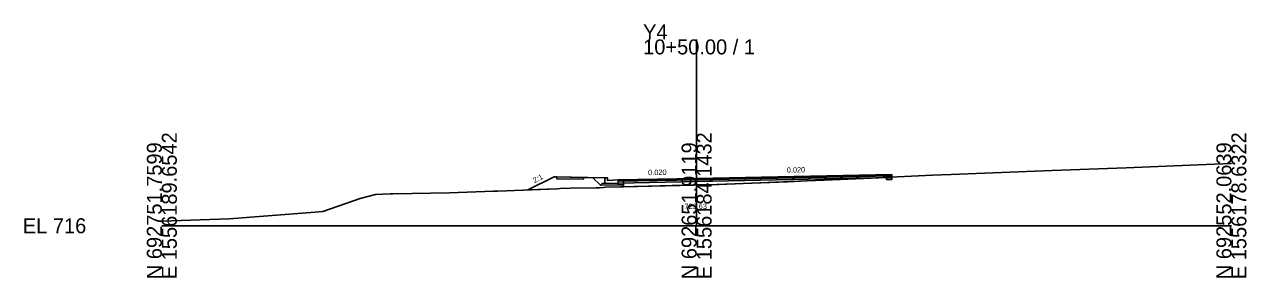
# Model space of a CAD drawing. Extents: x -26 to 203, y -10 to 1521.
# Drawn here: x -25.7 to 202.8, y -9.7 to 37.7 of the extents above; entities that cross this region are included whole.
import ezdxf

# ---------------------------------------------------------------- set-up
doc = ezdxf.new("R2010")
doc.units = 0
for name, color, linetype in [('Exist CMT Pavement', 7, 'Continuous'), ('Exist Cross Section Cell', 7, 'Continuous'), ('Exist XS Center Line Elevation Label', 7, 'Continuous'), ('Exist XS Ground Line', 7, 'Continuous'), ('Prop CMT Conc Surface', 7, 'Continuous'), ('Prop CMT Concrete Structures', 7, 'Continuous'), ('Prop CMT Pvmt Course 1', 7, 'Continuous'), ('Prop CMT Pvmt Course 1 CG', 7, 'Continuous'), ('Prop CMT Pvmt Course 2', 7, 'Continuous'), ('Prop CMT Pvmt Course 3', 7, 'Continuous'), ('Prop CMT Pvmt Surface', 7, 'Continuous'), ('Prop CMT Slope Grass', 7, 'Continuous'), ('Prop CMT Subgrade Earthwork', 7, 'Continuous'), ('Prop XS Earthwork Shape', 7, 'Continuous'), ('Prop XS SE Text', 7, 'Continuous'), ('Prop XS Side Slope Text', 7, 'Continuous')]:
    doc.layers.add(name, color=color, linetype=linetype)

msp = doc.modelspace()

# ---------------------------------------------------------------- linework, layer by layer
at = {"layer": 'Exist CMT Pavement'}
for p, q in [((86.34, 7.3), (102.09, 7.68)), ((102.09, 7.68), (117, 8.23)), ((117, 8.23), (120.67, 8.37)), ((120.67, 8.37), (135.49, 9.05))]:
    msp.add_line(p, q, dxfattribs=at)
at = {"layer": 'Exist Cross Section Cell'}
for p, q in [((100, 0), (100, 34.85)), ((0, 0), (100, 0)), ((100, 0), (200, 0))]:
    msp.add_line(p, q, dxfattribs=at)
at = {"layer": 'Exist XS Ground Line'}
msp.add_lwpolyline([(0, 0.86), (12.59, 1.28), (27.87, 2.46), (30.08, 2.69), (37.1, 5.09), (39.98, 5.86), (42.7, 5.95), (43.2, 5.97), (53.82, 6.17), (62.02, 6.47), (62.76, 6.48), (73.98, 6.9), (75.05, 7.01), (75.58, 6.98), (76.44, 7), (81.17, 7.11), (81.83, 7.11), (82.56, 7.14), (82.96, 7.21), (85.74, 7.28), (88.27, 7.36), (88.64, 7.37), (100, 7.63), (104.18, 7.73), (113.33, 8.09), (120.67, 8.37), (125.41, 8.59), (138.9, 9.21), (144.1, 9.43), (147.58, 9.56), (166.4, 10.31), (180.32, 10.86), (195.29, 11.45), (200, 11.62)], dxfattribs=at)
at = {"layer": 'Prop CMT Conc Surface'}
for points in [[(78.84, 9.03), (73.84, 9.13)], [(83.34, 8.44), (83.34, 8.94), (82.84, 8.94)], [(85.34, 8.56), (83.34, 8.44)]]:
    msp.add_lwpolyline(points, dxfattribs=at)
at = {"layer": 'Prop CMT Concrete Structures'}
for points in [[(73.84, 8.8), (73.84, 9.13)], [(73.84, 9.13), (78.84, 9.03)], [(78.84, 8.7), (73.84, 8.8)], [(78.84, 9.03), (78.84, 8.7)], [(85.34, 8.56), (83.34, 8.44), (83.34, 8.94), (82.84, 8.94)], [(82.84, 8.94), (82.84, 7.93), (85.34, 7.98)], [(85.34, 7.98), (85.34, 8.56)]]:
    msp.add_lwpolyline(points, dxfattribs=at)
at = {"layer": 'Prop CMT Pvmt Course 1'}
for p, q in [((100, 8.73), (135.49, 9.44)), ((135.49, 9.44), (135.49, 9.32)), ((86.34, 8.46), (100, 8.73)), ((86.34, 8.46), (86.34, 8.33))]:
    msp.add_line(p, q, dxfattribs=at)
for points in [[(100, 8.86), (136.49, 9.59)], [(136.49, 9.34), (100, 8.61)], [(136.49, 9.59), (136.49, 9.34)], [(136.49, 9.34), (136.49, 9.59)], [(85.34, 8.56), (85.34, 8.31)], [(100, 8.86), (100, 8.61)], [(100, 8.61), (100, 8.86)]]:
    msp.add_lwpolyline(points, dxfattribs=at)
for points in [[(136.49, 9.34), (136.49, 9.46), (136.49, 9.46), (136.49, 9.34)], [(100, 8.61), (100, 8.73), (100, 8.73), (100, 8.61)]]:
    msp.add_lwpolyline(points, close=True, dxfattribs=at)
at = {"layer": 'Prop CMT Pvmt Course 1 CG'}
for points in [[(85.34, 7.98), (82.34, 7.92), (82, 7.58)], [(82, 7.58), (85.34, 7.65)], [(85.34, 7.65), (85.34, 7.98)]]:
    msp.add_lwpolyline(points, dxfattribs=at)
at = {"layer": 'Prop CMT Pvmt Course 2'}
for p, q in [((135.49, 9.32), (135.49, 8.98)), ((85.34, 8.31), (100, 8.61)), ((86.34, 8.33), (86.34, 8))]:
    msp.add_line(p, q, dxfattribs=at)
for points in [[(100, 8.61), (136.49, 9.34)], [(136.49, 9.34), (136.49, 9.09)], [(136.49, 9.09), (136.49, 9.34)], [(136.49, 9.09), (136.49, 9.34)], [(136.49, 9), (136.49, 9.34)], [(85.34, 8.31), (85.34, 7.98)], [(132.84, 8.93), (100, 8.27)], [(100, 8.61), (100, 8.36)], [(100, 8.36), (100, 8.61)], [(100, 8.36), (100, 8.61)], [(100, 8.27), (100, 8.61)], [(136.49, 9), (135.49, 8.98)]]:
    msp.add_lwpolyline(points, dxfattribs=at)
at = {"layer": 'Prop CMT Pvmt Course 3'}
for p, q in [((85.34, 7.98), (100, 8.27)), ((86.34, 8), (86.34, 7.67))]:
    msp.add_line(p, q, dxfattribs=at)
for points in [[(85.34, 7.98), (85.34, 7.65)], [(100, 8.27), (132.84, 8.93)], [(135.49, 8.98), (136.49, 9)], [(136.49, 9.09), (136.49, 8.71)], [(136.49, 8.71), (136.49, 9.09)], [(136.49, 8.67), (136.49, 9)]]:
    msp.add_lwpolyline(points, dxfattribs=at)
at = {"layer": 'Prop CMT Pvmt Surface'}
for p, q in [((136.49, 9.59), (136.49, 9.1)), ((85.34, 8.56), (100, 8.86))]:
    msp.add_line(p, q, dxfattribs=at)
msp.add_lwpolyline([(100, 8.86), (136.49, 9.59)], dxfattribs=at)
at = {"layer": 'Prop CMT Slope Grass'}
msp.add_line((68.46, 6.69), (73.34, 9.13), dxfattribs=at)
msp.add_lwpolyline([(82.84, 8.94), (73.34, 9.13)], dxfattribs=at)
at = {"layer": 'Prop CMT Subgrade Earthwork'}
for p, q in [((85.34, 7.65), (86.34, 7.67)), ((86.34, 7.67), (86.34, 7.3)), ((135.49, 9.05), (135.49, 8.65)), ((136.49, 8.67), (135.49, 8.65)), ((136.49, 8.67), (136.49, 9.1))]:
    msp.add_line(p, q, dxfattribs=at)
msp.add_lwpolyline([(85.34, 7.65), (82, 7.58), (80.59, 8.99)], dxfattribs=at)
at = {"layer": 'Prop XS Earthwork Shape'}
for points in [[(82.56, 7.14), (82.96, 7.21), (85.74, 7.28), (86.34, 7.3), (86.34, 7.67), (85.34, 7.65), (82, 7.58), (80.59, 8.99), (78.84, 9.03), (78.84, 8.7), (73.84, 8.8), (73.84, 9.13), (73.34, 9.13), (68.46, 6.69), (73.98, 6.9), (75.05, 7.01), (75.58, 6.98), (76.44, 7), (81.17, 7.11), (81.83, 7.11)], [(100, 7.63), (102.09, 7.68), (86.34, 7.3), (88.27, 7.36), (88.64, 7.37)], [(104.18, 7.73), (113.33, 8.09), (117, 8.23), (102.09, 7.68)], [(125.41, 8.59), (135.49, 9.05), (120.67, 8.37)], [(136.49, 8.67), (136.49, 9.1), (135.49, 9.05), (135.49, 8.65)]]:
    msp.add_lwpolyline(points, close=True, dxfattribs=at)

# ---------------------------------------------------------------- texts
at = {"layer": 'Exist Cross Section Cell'}
for s, p in [('Y4', (90, 34.85)), ('10+50.00 / 1', (90, 32.05)), ('EL 716', (-26, -1.4))]:
    msp.add_text(s, height=2.8, dxfattribs=at).set_placement(p)
for s, p in [('E 1556189.6542', (2.8, -10)), ('E 1556184.1432', (102.8, -10)), ('E 1556178.6322', (202.8, -10)), ('N 692751.7599', (0, -10)), ('N 692651.9119', (100, -10)), ('N 692552.0639', (200, -10))]:
    msp.add_text(s, height=2.8, rotation=90, dxfattribs=at).set_placement(p)
at = {"layer": 'Exist XS Center Line Elevation Label'}
msp.add_text('723.63', height=1, dxfattribs=at).set_placement((97.71, 3.13))
at = {"layer": 'Prop XS SE Text'}
for rotation, p in [(0.843, (90.93, 9.46)), (1.1458, (116.86, 9.92))]:
    msp.add_text('0.020', height=1, rotation=rotation, dxfattribs=at).set_placement(p)
at = {"layer": 'Prop XS Side Slope Text'}
msp.add_text('2:1', height=1, rotation=26.5651, dxfattribs=at).set_placement((69.68, 7.96))

doc.saveas('drawing.dxf')
